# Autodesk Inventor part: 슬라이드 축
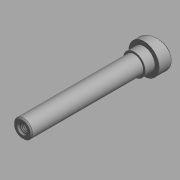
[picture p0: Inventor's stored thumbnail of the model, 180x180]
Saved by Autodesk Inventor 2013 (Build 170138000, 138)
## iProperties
Created: 2015-11
Part Number: 슬라이드 축
Document SubType Name: 모델링
Designer: mdu
Mass: 19.8501 g
Surface Area: 63.0734 cm^2
Volume: 19.8501 cm^3
Density: 1 g/cm^3
Material: 스테인리스강
변환 표준: STEP AP214IS
파일 이름: C:\Users\SeoGD\Desktop\?쒗뿕\異?stp
전처리기: Build: 253, Release: 2010 SP1 - Date: Wed 07/29/2009
전송 단위: 밀리미터
불확실성: 0.01
Author: mdu
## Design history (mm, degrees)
sketch "스케치1"
  geometry: L1 (0, 100)-(7.5, 100); L2 (7.5, 100)-(7.5, 0); L3 (7.5, 0)-(12.5, 0); L4 (12.5, 0)-(12.5, -17); L5 (12.5, -17)-(0, -17); L6 (0, -17)-(0, 100); 1 further point
  constraints: 12 end point, 2 parallel, 2 point on line, 1 perpendicular, 1 vertical
  dimensions: "d0" = 100 distance from line of L1 point (0, 0); "d1" = 15 diameter of L2 L6; "d2" = 25 diameter of L4 L6; "d3" = 17 distance of L3.end L4.end
revolve "회전1" sketch "스케치1" stored, may be unused: angle "d4" = 90 deg
sketch "스케치2"
  geometry: L1 (12.5, 0)-(12.5, -17) reference; L2 (-12.5, -17)-(12.5, -17) reference; L3 (-12.5, 0)-(-12.5, -17) reference; L4 (12.5, -5)-(-12.5, -11.699); L5 (-12.5, 0)-(12.5, 0) reference; 1 further point
  constraints: 2 end point, 2 point on line
  dimensions: "d5" = 75 deg angle of L1 L4; "d6" = 5 distance from line of L4.start L5
extrude "돌출1" cut sketch "스케치2" stored distance "d7" = 10; taper "d8" = 0 deg
chamfer "모따기1" distance "d9" = 1; stored, may be unused: second distance "d10" = 2, angle "d11" = 45 deg
fillet "모깎기1" dims "d12" = 0.5
hole "구멍1" diameter "d15" = 6.647; stored, may be unused: countersink angle "d19" = 90 deg, drill point angle "d21" = 118 deg; dims "d13" = 10, "d14" = 10, "d16" = 17, "d17" = 4, "d18" = 2, "d20" = 20
chamfer "모따기2" distance "d22" = 1; stored, may be unused: second distance "d23" = 2, angle "d24" = 45 deg
sketch "스케치3"
  geometry: C1 r 9 at (0, 0); 1 further point
  constraints: 1 centre point, 1 coincident
  dimensions: "d25" = 18 diameter of C1
extrude "돌출2" join sketch "스케치3" distance "d26" = 8; taper "d27" = 0 deg
node "솔리드1"
node "솔리드 본체"
node "곡면 본체"
node "솔리드2"
